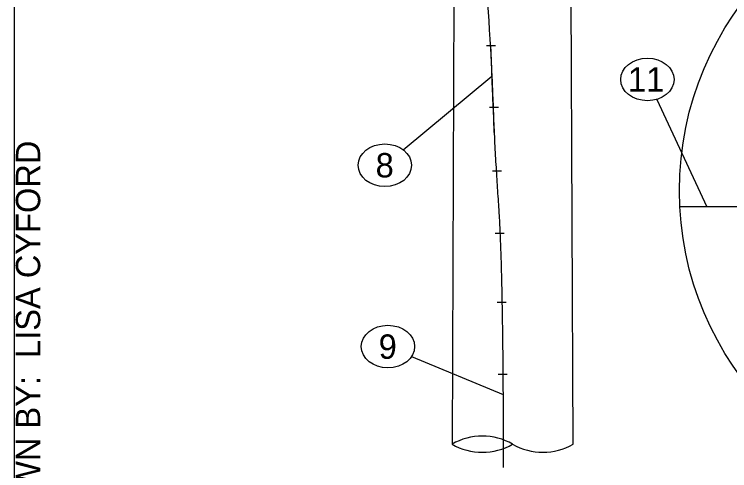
# Model space of a CAD drawing. Extents: x 99862 to 104211, y 98939 to 102076.
# Drawn here: x 99862 to 100331.4, y 101416.1 to 101715.8 of the extents above; entities that cross this region are included whole.
import ezdxf

# ---------------------------------------------------------------- set-up
doc = ezdxf.new("R2010")
doc.units = 0
for name, color, linetype in [('Level 1', 7, 'Continuous'), ('Level 11', 7, 'Continuous'), ('Level 12', 7, 'Continuous'), ('Level 15', 7, 'Continuous'), ('Level 20', 7, 'Continuous'), ('Level 62', 7, 'Continuous')]:
    doc.layers.add(name, color=color, linetype=linetype)

msp = doc.modelspace()

# ---------------------------------------------------------------- linework, layer by layer
at = {"layer": 'Level 1'}
for p, q in [((100151.45, 101972.17), (100149.21, 101433.5)), ((100228.7, 101433.5), (100227.29, 101770.61))]:
    msp.add_line(p, q, dxfattribs=at)
msp.add_lwpolyline([(99862, 99999.5), (103151, 99999.5), (103151, 102075.5), (99862, 102075.5)], close=True, dxfattribs=at)
for centre, start, end in [((100169.08, 101399.08), 60, 120), ((100169.08, 101467.92), 240, 300), ((100208.82, 101467.92), 240, 300)]:
    msp.add_arc(centre, 39.74, start, end, dxfattribs=at)
at = {"layer": 'Level 11'}
for p, q in [((100171.75, 101695.38), (100177.75, 101695.38)), ((100173.72, 101654.91), (100179.72, 101654.91)), ((100175.76, 101613.06), (100181.76, 101613.06)), ((100177.43, 101572.12), (100183.43, 101572.12)), ((100178.73, 101526.73), (100184.73, 101526.73)), ((100179.41, 101479.6), (100185.41, 101479.6))]:
    msp.add_line(p, q, dxfattribs=at)
msp.add_open_spline([(100174.49, 101695.59), (100176.48, 101635.07), (100182.79, 101546.25), (100182.79, 101418.14)], degree=2, dxfattribs=at)
at = {"layer": 'Level 12'}
msp.add_line((100394.28, 101589.38), (100298.68, 101589.38), dxfattribs=at)
msp.add_open_spline([(100176.93, 101638.26), (100173.89, 101734.54), (100164.15, 101799.98), (100138.47, 101825.12), (100098.36, 101838.8)], degree=3, dxfattribs=at)
at = {"layer": 'Level 15'}
for p, q in [((100117.22, 101626.76), (100175.27, 101675.11)), ((100283.5, 101659.89), (100316.31, 101589.38)), ((100122.6, 101491), (100182.76, 101466.1))]:
    msp.add_line(p, q, dxfattribs=at)
msp.add_circle((100504.52, 101599.96), 206.11, dxfattribs=at)
at = {"layer": 'Level 20'}
for centre in [(100277.4, 101673.01), (100105.1, 101616.66), (100107.16, 101497.59)]:
    msp.add_ellipse(centre, major_axis=(-17.5, 0), ratio=0.8, dxfattribs=at)

# ---------------------------------------------------------------- texts
for s, p in [('11', (100264.67, 101665.01)), ('8', (100099.08, 101608.67)), ('9', (100101.07, 101489.59))]:
    msp.add_text(s, height=16, dxfattribs=at).set_placement(p)
at = {"layer": 'Level 62'}
msp.add_text('DRAWN BY:  LISA CYFORD', height=16, rotation=90, dxfattribs=at).set_placement((99879, 101357.03))

doc.saveas('drawing.dxf')
